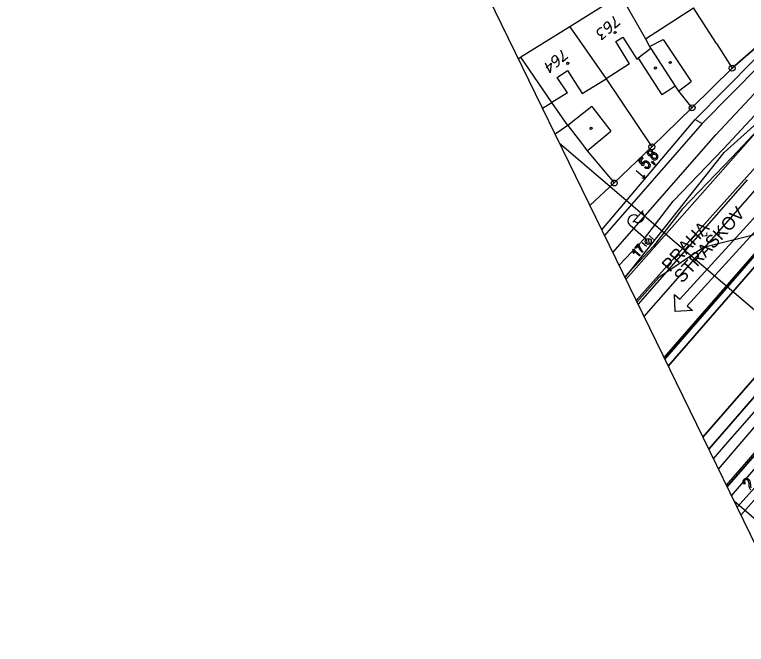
# Model space of a CAD drawing. Extents: x -747602 to 748961, y -1003706 to 1004048.
# Drawn here: x -747602.2 to -747481.5, y -1003706.2 to -1003602.4 of the extents above; entities that cross this region are included whole.
import ezdxf

# ---------------------------------------------------------------- set-up
doc = ezdxf.new("R2010")
doc.units = 0
for name, color, linetype in [('Formáty', 7, 'Continuous'), ('Rozpiska 1 000 A', 7, 'Continuous'), ('Telematika', 7, 'Continuous'), ('Vrstva 1', 7, 'Continuous'), ('Vrstva 11', 7, 'Continuous'), ('Vrstva 12', 7, 'Continuous'), ('Vrstva 13', 7, 'Continuous'), ('Vrstva 17', 7, 'Continuous'), ('Vrstva 2', 7, 'Continuous'), ('Vrstva 23', 7, 'Continuous'), ('Vrstva 25', 7, 'Continuous'), ('Vrstva 4', 7, 'Continuous'), ('Vrstva 5', 7, 'Continuous'), ('Vrstva 50', 7, 'Continuous'), ('Vrstva 51', 7, 'Continuous'), ('Vrstva 53', 7, 'Continuous'), ('Vrstva 6', 7, 'Continuous'), ('Vrstva 8', 7, 'Continuous')]:
    doc.layers.add(name, color=color, linetype=linetype)

msp = doc.modelspace()

# ---------------------------------------------------------------- linework, layer by layer
at = {"layer": 'Formáty'}
msp.add_line((-747472.03, -1003706.23), (-747602.16, -1003439.26), dxfattribs=at)
at = {"layer": 'Rozpiska 1 000 A'}
for p, q in [((-747492.5, -1003649.3), (-747479.76, -1003635.33)), ((-747478.55, -1003636.43), (-747491.29, -1003650.4)), ((-747493.23, -1003651.32), (-747493.36, -1003648.51)), ((-747493.36, -1003648.51), (-747492.5, -1003649.3)), ((-747490.42, -1003651.19), (-747493.23, -1003651.32)), ((-747491.29, -1003650.4), (-747490.42, -1003651.19))]:
    msp.add_line(p, q, dxfattribs=at)
at = {"layer": 'Telematika'}
for p, q in [((-747486.12, -1003677.32), (-747468.66, -1003656.84)), ((-747483.97, -1003681.74), (-747474.75, -1003670.91))]:
    msp.add_line(p, q, dxfattribs=at)
at = {"layer": 'Vrstva 1'}
for p, q in [((-747502.25, -1003599.12), (-747510.61, -1003604.35)), ((-747502.25, -1003599.12), (-747498.15, -1003606.35)), ((-747486.45, -1003607.15), (-747490.21, -1003601.27)), ((-747510.61, -1003604.35), (-747518.72, -1003609.38)), ((-747510.61, -1003604.35), (-747504.62, -1003612.94)), ((-747475.84, -1003604.17), (-747483.87, -1003611.19)), ((-747498.15, -1003606.35), (-747497.48, -1003607.6)), ((-747497.48, -1003607.6), (-747497.29, -1003607.96)), ((-747497.29, -1003607.96), (-747493.26, -1003614.15)), ((-747494.94, -1003659.23), (-747449.77, -1003607.15)), ((-747486.45, -1003607.15), (-747483.87, -1003611.19)), ((-747519.12, -1003609.63), (-747518.72, -1003609.38)), ((-747513.57, -1003616.84), (-747518.72, -1003609.38)), ((-747483.87, -1003611.19), (-747490.48, -1003617.74)), ((-747504.62, -1003612.94), (-747502.35, -1003616.33)), ((-747493.26, -1003614.15), (-747492.71, -1003614.98)), ((-747486.55, -1003622.19), (-747478.47, -1003613.53)), ((-747492.71, -1003614.98), (-747490.48, -1003617.74)), ((-747502.35, -1003616.33), (-747497.1, -1003624.16)), ((-747437.34, -1003616.03), (-747487.73, -1003674.02)), ((-747510.95, -1003620.63), (-747513.57, -1003616.84)), ((-747490.48, -1003617.74), (-747497.1, -1003624.16)), ((-747510.95, -1003620.63), (-747508.86, -1003623.36)), ((-747503.54, -1003641.6), (-747486.55, -1003622.19)), ((-747508.86, -1003623.36), (-747508.35, -1003624.03)), ((-747508.35, -1003624.03), (-747507.74, -1003624.83)), ((-747507.74, -1003624.83), (-747503.31, -1003630.13)), ((-747497.1, -1003624.16), (-747503.31, -1003630.13)), ((-747503.31, -1003630.13), (-747507.31, -1003633.85)), ((-747484.94, -1003673.33), (-747471.5, -1003657.87)), ((-747484.7, -1003680.25), (-747475.51, -1003669.66)), ((-747486.95, -1003675.64), (-747484.94, -1003673.33)), ((-747482.41, -1003684.94), (-747477.23, -1003678.98))]:
    msp.add_line(p, q, dxfattribs=at)
at = {"layer": 'Vrstva 11'}
msp.add_lwpolyline([(-747481.66, -1003679.67), (-747481.82, -1003679.81)], dxfattribs=at)
for points in [[(-747481.82, -1003679.81), (-747482.02, -1003679.6), (-747482.04, -1003679.4), (-747482.06, -1003679.2), (-747481.91, -1003679.02), (-747481.74, -1003678.83), (-747481.53, -1003678.85), (-747481.32, -1003678.86), (-747481.15, -1003679), (-747481.01, -1003679.13), (-747480.94, -1003679.32), (-747480.88, -1003679.51), (-747480.84, -1003679.91), (-747480.82, -1003680.17), (-747480.81, -1003680.25), (-747480.79, -1003680.34), (-747480.76, -1003680.41)], [(-747480.76, -1003680.77), (-747480.88, -1003680.68), (-747480.95, -1003680.5), (-747481.03, -1003680.31), (-747481.05, -1003679.97), (-747481.08, -1003679.57), (-747481.14, -1003679.41), (-747481.19, -1003679.24), (-747481.29, -1003679.15), (-747481.41, -1003679.05), (-747481.54, -1003679.06), (-747481.67, -1003679.06), (-747481.76, -1003679.16), (-747481.85, -1003679.27), (-747481.83, -1003679.4), (-747481.81, -1003679.54), (-747481.66, -1003679.67)]]:
    msp.add_open_spline(points, degree=3, dxfattribs=at)
at = {"layer": 'Vrstva 12'}
for p, q in [((-747495.09, -1003658.93), (-747476.73, -1003637.84)), ((-747476.7, -1003637.81), (-747495.07, -1003658.98)), ((-747494.41, -1003660.33), (-747475.62, -1003638.7)), ((-747475.23, -1003656.59), (-747488.69, -1003672.05)), ((-747473.55, -1003657.72), (-747487.72, -1003674.05)), ((-747487.72, -1003674.05), (-747473.61, -1003657.75))]:
    msp.add_line(p, q, dxfattribs=at)
at = {"layer": 'Vrstva 13'}
for p, q in [((-747489.94, -1003619.65), (-747480.2, -1003609.78)), ((-747479.23, -1003610.66), (-747488.8, -1003620.31)), ((-747501.38, -1003646.03), (-747475.73, -1003617)), ((-747485.28, -1003624.51), (-747478.67, -1003617.42)), ((-747476.96, -1003618.5), (-747483.83, -1003625.89)), ((-747505.35, -1003637.88), (-747489.94, -1003619.65)), ((-747489.94, -1003619.65), (-747488.8, -1003620.31)), ((-747488.8, -1003620.31), (-747504.9, -1003638.8)), ((-747477.28, -1003624.42), (-747499.68, -1003649.52)), ((-747493.59, -1003633.13), (-747485.28, -1003624.51)), ((-747483.83, -1003625.89), (-747492.08, -1003634.44)), ((-747499.67, -1003628.06), (-747498.16, -1003629.37)), ((-747499.35, -1003650.19), (-747481.3, -1003629.64)), ((-747479.8, -1003630.95), (-747498.4, -1003652.14)), ((-747498.33, -1003639.28), (-747493.59, -1003633.13)), ((-747492.08, -1003634.44), (-747496.81, -1003640.58)), ((-747502.51, -1003643.71), (-747498.33, -1003639.28)), ((-747496.81, -1003640.58), (-747501.57, -1003645.63))]:
    msp.add_line(p, q, dxfattribs=at)
for points in [[(-747498.41, -1003627.19), (-747498.56, -1003627.31), (-747499.23, -1003626.51), (-747498.69, -1003625.9), (-747498.51, -1003626.05), (-747498.95, -1003626.55), (-747498.6, -1003626.97)], [(-747496.95, -1003626.91), (-747497.16, -1003626.73), (-747497.01, -1003626.56), (-747496.8, -1003626.74)], [(-747496.88, -1003626.83), (-747496.95, -1003626.91)], [(-747496.63, -1003627.14), (-747496.75, -1003627.12)], [(-747498.26, -1003627.61), (-747498.14, -1003627.44)], [(-747498.73, -1003629.27), (-747498.16, -1003629.37), (-747498.34, -1003628.82)]]:
    msp.add_lwpolyline(points, dxfattribs=at)
for points in [[(-747497.22, -1003625.57), (-747497.34, -1003625.63), (-747497.46, -1003625.61), (-747497.58, -1003625.59), (-747497.69, -1003625.49), (-747497.86, -1003625.34), (-747497.88, -1003625.14), (-747497.9, -1003624.95), (-747497.77, -1003624.79), (-747497.63, -1003624.64), (-747497.43, -1003624.63), (-747497.23, -1003624.63), (-747497.06, -1003624.78), (-747496.95, -1003624.88), (-747496.92, -1003624.99), (-747496.88, -1003625.1), (-747496.92, -1003625.23), (-747496.78, -1003625.15), (-747496.63, -1003625.18), (-747496.47, -1003625.21), (-747496.33, -1003625.33), (-747496.13, -1003625.51), (-747496.1, -1003625.74), (-747496.08, -1003625.96), (-747496.23, -1003626.14), (-747496.38, -1003626.31), (-747496.61, -1003626.32), (-747496.84, -1003626.32), (-747497.04, -1003626.14), (-747497.2, -1003626.01), (-747497.24, -1003625.86), (-747497.28, -1003625.71), (-747497.22, -1003625.57)], [(-747497.56, -1003625.33), (-747497.45, -1003625.42), (-747497.33, -1003625.42), (-747497.22, -1003625.42), (-747497.14, -1003625.34), (-747497.07, -1003625.25), (-747497.08, -1003625.14), (-747497.1, -1003625.02), (-747497.2, -1003624.93), (-747497.3, -1003624.84), (-747497.42, -1003624.84), (-747497.54, -1003624.85), (-747497.61, -1003624.93), (-747497.69, -1003625.01), (-747497.67, -1003625.12), (-747497.66, -1003625.24), (-747497.56, -1003625.33)], [(-747496.91, -1003625.99), (-747496.77, -1003626.11), (-747496.62, -1003626.11), (-747496.47, -1003626.11), (-747496.38, -1003626), (-747496.29, -1003625.9), (-747496.31, -1003625.75), (-747496.33, -1003625.61), (-747496.46, -1003625.49), (-747496.6, -1003625.37), (-747496.75, -1003625.37), (-747496.9, -1003625.37), (-747496.99, -1003625.47), (-747497.08, -1003625.58), (-747497.06, -1003625.72), (-747497.04, -1003625.87), (-747496.91, -1003625.99)], [(-747498.6, -1003626.97), (-747498.6, -1003626.78), (-747498.49, -1003626.65), (-747498.35, -1003626.5), (-747498.12, -1003626.5), (-747497.89, -1003626.5), (-747497.66, -1003626.69), (-747497.44, -1003626.89), (-747497.39, -1003627.14), (-747497.33, -1003627.39), (-747497.5, -1003627.59), (-747497.64, -1003627.75), (-747497.85, -1003627.76), (-747498.05, -1003627.77), (-747498.26, -1003627.61)], [(-747498.14, -1003627.44), (-747497.98, -1003627.55), (-747497.85, -1003627.54), (-747497.73, -1003627.54), (-747497.65, -1003627.45), (-747497.56, -1003627.35), (-747497.59, -1003627.18), (-747497.62, -1003627.02), (-747497.79, -1003626.87), (-747497.95, -1003626.73), (-747498.11, -1003626.72), (-747498.26, -1003626.72), (-747498.36, -1003626.84), (-747498.42, -1003626.9), (-747498.44, -1003627), (-747498.45, -1003627.09), (-747498.41, -1003627.19)], [(-747496.75, -1003627.12), (-747496.73, -1003627.05), (-747496.76, -1003626.98), (-747496.79, -1003626.92), (-747496.88, -1003626.83)], [(-747496.8, -1003626.74), (-747496.68, -1003626.85), (-747496.64, -1003626.95), (-747496.61, -1003627.04), (-747496.63, -1003627.14)]]:
    msp.add_open_spline(points, degree=3, dxfattribs=at)
at = {"layer": 'Vrstva 17'}
for p, q in [((-747496.8, -1003639.45), (-747497.53, -1003638.79)), ((-747497.97, -1003640.62), (-747498.72, -1003640.03))]:
    msp.add_line(p, q, dxfattribs=at)
at = {"layer": 'Vrstva 2'}
for points in [[(-747502.34, -1003603.9), (-747503.15, -1003604.6), (-747503.14, -1003604.5), (-747503.12, -1003603.94), (-747503.16, -1003603.48), (-747503.33, -1003603.04), (-747503.51, -1003602.66)], [(-747504.32, -1003605.36), (-747504.14, -1003605.4), (-747504.02, -1003605.35), (-747503.88, -1003605.23), (-747503.81, -1003605.1), (-747503.77, -1003605.03), (-747503.75, -1003604.95), (-747503.74, -1003604.63), (-747503.84, -1003604.29), (-747503.92, -1003604.13), (-747504.14, -1003603.8), (-747504.27, -1003603.65), (-747504.36, -1003603.63), (-747504.51, -1003603.61), (-747504.56, -1003603.62), (-747504.69, -1003603.68), (-747504.82, -1003603.79), (-747504.9, -1003603.9), (-747504.96, -1003603.98), (-747504.99, -1003604.15), (-747504.95, -1003604.4), (-747504.89, -1003604.53), (-747504.82, -1003604.61), (-747504.66, -1003604.69), (-747504.57, -1003604.71), (-747504.47, -1003604.69), (-747504.32, -1003604.62), (-747504.23, -1003604.54), (-747504.14, -1003604.41), (-747504.1, -1003604.32), (-747504.05, -1003604.13), (-747504.03, -1003604.03), (-747504.03, -1003603.97)], [(-747504.66, -1003605.9), (-747505.37, -1003606.51), (-747505.33, -1003605.88), (-747505.21, -1003605.57), (-747505.39, -1003605.73), (-747505.44, -1003605.76), (-747505.47, -1003605.76), (-747505.5, -1003605.77), (-747505.53, -1003605.78), (-747505.59, -1003605.78), (-747505.64, -1003605.77), (-747505.69, -1003605.76), (-747505.72, -1003605.74), (-747505.8, -1003605.68), (-747505.87, -1003605.63), (-747505.89, -1003605.6), (-747505.93, -1003605.56), (-747505.97, -1003605.49), (-747505.99, -1003605.44), (-747506.02, -1003605.39), (-747506.04, -1003605.35), (-747506.04, -1003605.32), (-747506.05, -1003605.29), (-747506.06, -1003605.26), (-747506.06, -1003605.22), (-747506.07, -1003605.15), (-747506.06, -1003605.09), (-747506.06, -1003605.06), (-747506.05, -1003605.01), (-747506.04, -1003604.96), (-747506.01, -1003604.91), (-747506, -1003604.88), (-747505.95, -1003604.8), (-747505.89, -1003604.74), (-747505.86, -1003604.69), (-747505.79, -1003604.63), (-747505.7, -1003604.57), (-747505.66, -1003604.55), (-747505.62, -1003604.54), (-747505.58, -1003604.52), (-747505.54, -1003604.52), (-747505.49, -1003604.51), (-747505.4, -1003604.51), (-747505.34, -1003604.52)], [(-747512.93, -1003610.91), (-747512.76, -1003610.95), (-747512.64, -1003610.9), (-747512.5, -1003610.78), (-747512.43, -1003610.65), (-747512.39, -1003610.58), (-747512.36, -1003610.5), (-747512.36, -1003610.18), (-747512.46, -1003609.84), (-747512.54, -1003609.68), (-747512.75, -1003609.35), (-747512.88, -1003609.2), (-747512.98, -1003609.18), (-747513.13, -1003609.16), (-747513.18, -1003609.17), (-747513.3, -1003609.23), (-747513.43, -1003609.34), (-747513.52, -1003609.45), (-747513.57, -1003609.53), (-747513.6, -1003609.7), (-747513.57, -1003609.95), (-747513.51, -1003610.08), (-747513.44, -1003610.16), (-747513.27, -1003610.24), (-747513.19, -1003610.26), (-747513.08, -1003610.24), (-747512.94, -1003610.17), (-747512.84, -1003610.09), (-747512.76, -1003609.96), (-747512.71, -1003609.87), (-747512.66, -1003609.68), (-747512.65, -1003609.58), (-747512.64, -1003609.52)], [(-747510.96, -1003609.45), (-747511.77, -1003610.15), (-747511.76, -1003610.05), (-747511.74, -1003609.49), (-747511.78, -1003609.03), (-747511.95, -1003608.59), (-747512.13, -1003608.21)], [(-747514.55, -1003611.14), (-747513.68, -1003610.38), (-747513.86, -1003611.95), (-747514.62, -1003610.36)]]:
    msp.add_lwpolyline(points, dxfattribs=at)
at = {"layer": 'Vrstva 23'}
for p, q in [((-747475.62, -1003638.7), (-747494.41, -1003660.33)), ((-747488.69, -1003672.05), (-747475.23, -1003656.59))]:
    msp.add_line(p, q, dxfattribs=at)
at = {"layer": 'Vrstva 25'}
for p, q in [((-747500.24, -1003636.62), (-747498.52, -1003634.67)), ((-747498.06, -1003639.45), (-747500.7, -1003637.15)), ((-747497.89, -1003640.24), (-747497.95, -1003639.36)), ((-747497.52, -1003640.25), (-747497.58, -1003639.3))]:
    msp.add_line(p, q, dxfattribs=at)
for points in [[(-747499.76, -1003640.89), (-747499.89, -1003640.77), (-747499.37, -1003640.18), (-747499.26, -1003640.27)], [(-747499.36, -1003640.44), (-747499.76, -1003640.89)], [(-747500.24, -1003641.13), (-747500.17, -1003641.06), (-747499.04, -1003642.05)], [(-747500.05, -1003641.76), (-747500.19, -1003641.65)], [(-747499.04, -1003642.05), (-747499.14, -1003642.16), (-747500.02, -1003641.39)], [(-747498.56, -1003641.5), (-747498.66, -1003641.62)]]:
    msp.add_lwpolyline(points, dxfattribs=at)
msp.add_circle((-747497.69, -1003639.78), 0.5, dxfattribs=at)
for centre, start, end in [((-747500.04, -1003636.4), 48.8044, 228.8044), ((-747499.37, -1003635.65), 228.1018, 49.507)]:
    msp.add_arc(centre, 1, start, end, dxfattribs=at)
for points in [[(-747498.66, -1003641.62), (-747498.8, -1003641.49), (-747498.95, -1003641.29), (-747499.11, -1003641.08), (-747499.21, -1003640.85), (-747499.32, -1003640.63), (-747499.36, -1003640.44)], [(-747499.26, -1003640.27), (-747499.2, -1003640.56), (-747499.01, -1003640.9), (-747498.82, -1003641.25), (-747498.56, -1003641.5)], [(-747500.19, -1003641.65), (-747500.16, -1003641.5), (-747500.17, -1003641.36), (-747500.19, -1003641.22), (-747500.24, -1003641.13)], [(-747500.02, -1003641.39), (-747500.01, -1003641.47), (-747500.02, -1003641.58), (-747500.03, -1003641.69), (-747500.05, -1003641.76)]]:
    msp.add_open_spline(points, degree=3, dxfattribs=at)
at = {"layer": 'Vrstva 4'}
for p, q in [((-747498.15, -1003606.35), (-747490.21, -1003601.27)), ((-747503.05, -1003606.81), (-747501.89, -1003606.06)), ((-747500.77, -1003610.46), (-747503.05, -1003606.81)), ((-747501.89, -1003606.06), (-747499.58, -1003609.71)), ((-747497.48, -1003607.6), (-747495.24, -1003606.45)), ((-747495.24, -1003606.45), (-747491.18, -1003612.56)), ((-747497.29, -1003607.96), (-747499.33, -1003609.56)), ((-747494.41, -1003660.33), (-747448.89, -1003607.94)), ((-747500.77, -1003610.46), (-747504.62, -1003612.94)), ((-747499.58, -1003609.71), (-747499.33, -1003609.56)), ((-747499.33, -1003609.56), (-747495.46, -1003615.62)), ((-747512.72, -1003612.71), (-747511, -1003611.59)), ((-747511, -1003611.59), (-747508.56, -1003615.4)), ((-747511.03, -1003615.24), (-747512.72, -1003612.71)), ((-747508.56, -1003615.4), (-747504.62, -1003612.94)), ((-747491.18, -1003612.56), (-747490.62, -1003613.39)), ((-747493.26, -1003614.15), (-747494.58, -1003615.03)), ((-747492.71, -1003614.98), (-747490.62, -1003613.39)), ((-747511.03, -1003615.24), (-747513.57, -1003616.84)), ((-747494.58, -1003615.03), (-747495.46, -1003615.62)), ((-747438.9, -1003614.77), (-747488.68, -1003672.07)), ((-747515.14, -1003617.8), (-747513.57, -1003616.84)), ((-747507.01, -1003617.52), (-747510.95, -1003620.63)), ((-747507.01, -1003617.52), (-747503.88, -1003621.6)), ((-747510.95, -1003620.63), (-747513.05, -1003622.09)), ((-747507.74, -1003624.83), (-747503.88, -1003621.6)), ((-747509.01, -1003630.29), (-747509.1, -1003630.18)), ((-747509.01, -1003630.29), (-747509.04, -1003630.32))]:
    msp.add_line(p, q, dxfattribs=at)
at = {"layer": 'Vrstva 5'}
for points in [[(-747503.13, -1003605.47), (-747503.29, -1003605.42), (-747503.32, -1003605.25), (-747503.19, -1003605.13), (-747503.02, -1003605.18), (-747502.99, -1003605.36)], [(-747510.93, -1003610.57), (-747511.1, -1003610.51), (-747511.13, -1003610.34), (-747510.99, -1003610.22), (-747510.83, -1003610.28), (-747510.8, -1003610.45)], [(-747494.04, -1003610.43), (-747494.2, -1003610.38), (-747494.23, -1003610.2), (-747494.09, -1003610.09), (-747493.93, -1003610.14), (-747493.9, -1003610.31)], [(-747496.47, -1003611.34), (-747496.64, -1003611.29), (-747496.67, -1003611.11), (-747496.53, -1003611), (-747496.36, -1003611.05), (-747496.33, -1003611.22)], [(-747507.09, -1003621.29), (-747507.26, -1003621.23), (-747507.29, -1003621.06), (-747507.15, -1003620.94), (-747506.99, -1003621), (-747506.96, -1003621.17)]]:
    msp.add_lwpolyline(points, close=True, dxfattribs=at)
at = {"layer": 'Vrstva 50'}
for p, q in [((-747484.68, -1003680.29), (-747478.17, -1003672.81)), ((-747483.05, -1003683.63), (-747477.52, -1003677.42)), ((-747467.22, -1003696.7), (-747483.54, -1003682.63))]:
    msp.add_line(p, q, dxfattribs=at)
at = {"layer": 'Vrstva 51'}
for p, q in [((-747485.2, -1003625.08), (-747471.71, -1003613.04)), ((-747501.52, -1003645.74), (-747485.2, -1003625.08)), ((-747476.73, -1003637.84), (-747488.56, -1003640.76)), ((-747488.56, -1003640.76), (-747495.95, -1003645.71)), ((-747495.95, -1003645.71), (-747499.56, -1003649.77))]:
    msp.add_line(p, q, dxfattribs=at)
at = {"layer": 'Vrstva 53'}
for p, q in [((-747483.87, -1003611.19), (-747475.84, -1003604.17)), ((-747490.48, -1003617.74), (-747483.87, -1003611.19)), ((-747497.1, -1003624.16), (-747490.48, -1003617.74)), ((-747503.31, -1003630.13), (-747497.1, -1003624.16)), ((-747507.31, -1003633.85), (-747503.31, -1003630.13)), ((-747475.66, -1003669.37), (-747484.82, -1003680))]:
    msp.add_line(p, q, dxfattribs=at)
at = {"layer": 'Vrstva 6'}
msp.add_line((-747512.32, -1003623.58), (-747466.45, -1003662.81), dxfattribs=at)
at = {"layer": 'Vrstva 8'}
for p, q in [((-747483.78, -1003611.11), (-747483.96, -1003611.26)), ((-747490.39, -1003617.66), (-747490.57, -1003617.82)), ((-747497.01, -1003624.09), (-747497.2, -1003624.24)), ((-747503.21, -1003630.05), (-747503.4, -1003630.21))]:
    msp.add_line(p, q, dxfattribs=at)
for points in [[(-747483.67, -1003611.65), (-747483.97, -1003611.67), (-747484.24, -1003611.52), (-747484.35, -1003611.24), (-747484.28, -1003610.94), (-747484.05, -1003610.73), (-747483.74, -1003610.71), (-747483.47, -1003610.86), (-747483.36, -1003611.15), (-747483.43, -1003611.45)], [(-747490.28, -1003618.2), (-747490.59, -1003618.23), (-747490.85, -1003618.08), (-747490.97, -1003617.79), (-747490.89, -1003617.49), (-747490.66, -1003617.29), (-747490.35, -1003617.26), (-747490.09, -1003617.42), (-747489.97, -1003617.7), (-747490.05, -1003618)], [(-747496.9, -1003624.63), (-747497.21, -1003624.65), (-747497.48, -1003624.5), (-747497.59, -1003624.21), (-747497.52, -1003623.91), (-747497.28, -1003623.71), (-747496.98, -1003623.68), (-747496.71, -1003623.84), (-747496.6, -1003624.12), (-747496.67, -1003624.42)], [(-747503.11, -1003630.59), (-747503.41, -1003630.62), (-747503.68, -1003630.46), (-747503.79, -1003630.18), (-747503.72, -1003629.88), (-747503.48, -1003629.67), (-747503.18, -1003629.65), (-747502.91, -1003629.8), (-747502.8, -1003630.09), (-747502.87, -1003630.39)]]:
    msp.add_lwpolyline(points, close=True, dxfattribs=at)

# ---------------------------------------------------------------- texts
at = {"layer": 'Rozpiska 1 000 A'}
for s, p in [('STRAŠKOV', (-747492.09, -1003646.77)), ('PRAHA', (-747494.1, -1003644.94))]:
    msp.add_text(s, height=2.136, rotation=47.6488, dxfattribs=at).set_placement(p)

doc.saveas('drawing.dxf')
